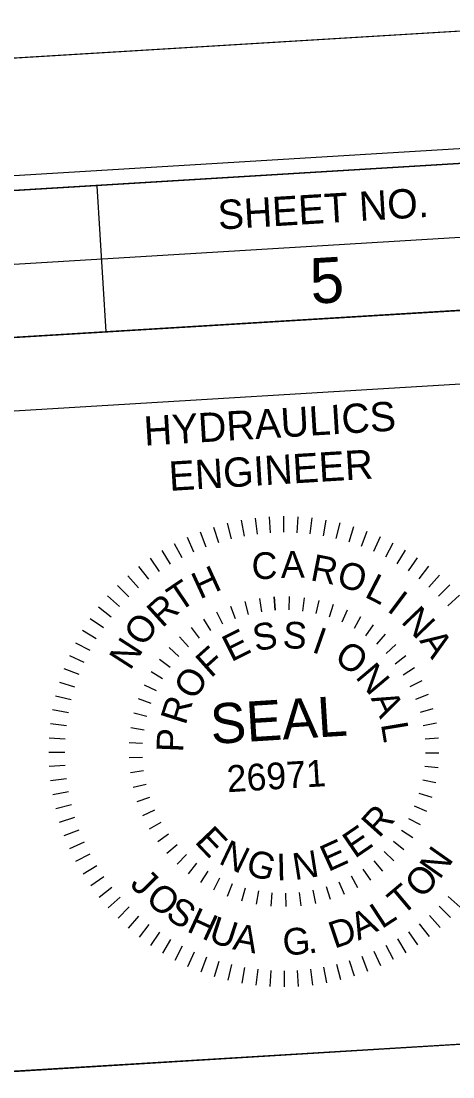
# Model space of a CAD drawing. Extents: x 2111349 to 2114115, y 669753 to 671326.
# Drawn here: x 2113745.9 to 2113819.6, y 670767.4 to 670947.5 of the extents above; entities that cross this region are included whole.
import ezdxf

# ---------------------------------------------------------------- set-up
doc = ezdxf.new("R2010")
doc.units = 0
for name, color, linetype in [('Default', 7, 'Continuous'), ('Exist Roads Curbs', 7, 'Continuous'), ('Exist Roads Curbs Text', 7, 'Continuous'), ('Exist Roads EOP Other Text', 7, 'Continuous'), ('Exist Utilities Power Transformer Cogo Comment', 7, 'Continuous'), ('Exist Utilities Telephone Test Hole SUE LOS A Text', 7, 'Continuous'), ('Exist Utilities Water Test Hole SUE LOS A Text', 7, 'Continuous')]:
    doc.layers.add(name, color=color, linetype=linetype)

msp = doc.modelspace()

# ---------------------------------------------------------------- linework, layer by layer
at = {"layer": 'Default'}
for p, q in [((2113781.1, 670861.87), (2113781.76, 670859.21)), ((2113783.47, 670862.38), (2113783.96, 670859.69)), ((2113785.86, 670862.75), (2113786.2, 670860.03)), ((2113788.28, 670862.97), (2113788.45, 670860.24)), ((2113790.7, 670863.05), (2113790.71, 670860.32)), ((2113793.13, 670862.98), (2113792.97, 670860.25)), ((2113795.54, 670862.77), (2113795.22, 670860.06)), ((2113797.94, 670862.41), (2113797.45, 670859.72)), ((2113800.31, 670861.91), (2113799.66, 670859.25)), ((2113776.47, 670860.42), (2113777.44, 670857.86)), ((2113778.76, 670861.21), (2113779.58, 670858.6)), ((2113802.65, 670861.26), (2113801.84, 670858.64)), ((2113804.94, 670860.47), (2113803.98, 670857.91)), ((2113772.06, 670858.41), (2113773.33, 670856)), ((2113774.23, 670859.49), (2113775.36, 670856.99)), ((2113807.19, 670859.55), (2113806.07, 670857.05)), ((2113809.37, 670858.49), (2113808.1, 670856.07)), ((2113769.94, 670857.22), (2113771.36, 670854.88)), ((2113811.48, 670857.3), (2113810.07, 670854.96)), ((2113767.91, 670855.9), (2113769.47, 670853.65)), ((2113813.52, 670855.99), (2113811.97, 670853.74)), ((2113815.48, 670854.56), (2113813.8, 670852.4)), ((2113764.1, 670852.9), (2113765.92, 670850.86)), ((2113765.96, 670854.46), (2113767.65, 670852.31)), ((2113817.34, 670853.01), (2113815.53, 670850.96)), ((2113762.34, 670851.24), (2113764.28, 670849.31)), ((2113819.11, 670851.35), (2113817.18, 670849.41)), ((2113760.68, 670849.47), (2113762.73, 670847.66)), ((2113789.13, 670849.31), (2113789.27, 670847.04)), ((2113789.27, 670847.04), (2113789.13, 670849.31)), ((2113791.69, 670849.35), (2113791.61, 670847.07)), ((2113794.24, 670849.14), (2113793.94, 670846.88)), ((2113820.78, 670849.59), (2113818.74, 670847.77)), ((2113759.13, 670847.6), (2113761.29, 670845.92)), ((2113781.65, 670847.74), (2113782.44, 670845.6)), ((2113784.09, 670848.51), (2113784.66, 670846.3)), ((2113786.59, 670849.03), (2113786.95, 670846.78)), ((2113796.75, 670848.69), (2113796.24, 670846.46)), ((2113799.21, 670847.99), (2113798.49, 670845.83)), ((2113757.7, 670845.64), (2113759.95, 670844.1)), ((2113779.29, 670846.74), (2113780.28, 670844.69)), ((2113801.59, 670847.06), (2113800.66, 670844.98)), ((2113803.87, 670845.9), (2113802.75, 670843.92)), ((2113774.93, 670844.09), (2113776.29, 670842.26)), ((2113777.05, 670845.52), (2113778.23, 670843.57)), ((2113806.03, 670844.53), (2113804.72, 670842.66)), ((2113756.38, 670843.61), (2113758.73, 670842.2)), ((2113772.96, 670842.46), (2113774.5, 670840.77)), ((2113808.05, 670842.96), (2113806.56, 670841.23)), ((2113755.2, 670841.49), (2113757.62, 670840.22)), ((2113771.16, 670840.65), (2113772.85, 670839.12)), ((2113809.9, 670841.2), (2113808.26, 670839.62)), ((2113754.14, 670839.31), (2113756.64, 670838.19)), ((2113769.53, 670838.67), (2113771.36, 670837.32)), ((2113811.58, 670839.27), (2113809.79, 670837.85)), ((2113753.22, 670837.07), (2113755.78, 670836.1)), ((2113768.11, 670836.55), (2113770.06, 670835.37)), ((2113813.06, 670837.19), (2113811.14, 670835.95)), ((2113752.43, 670834.77), (2113755.04, 670833.96)), ((2113814.34, 670834.97), (2113812.3, 670833.93)), ((2113766.9, 670834.3), (2113768.96, 670833.31)), ((2113751.78, 670832.44), (2113754.44, 670831.79)), ((2113765.91, 670831.94), (2113768.06, 670831.16)), ((2113815.39, 670832.64), (2113813.26, 670831.8)), ((2113751.28, 670830.06), (2113753.97, 670829.58)), ((2113765.16, 670829.5), (2113767.37, 670828.93)), ((2113816.21, 670830.22), (2113814.02, 670829.59)), ((2113750.92, 670827.67), (2113753.63, 670827.34)), ((2113816.8, 670827.73), (2113814.56, 670827.32)), ((2113764.64, 670826.99), (2113766.89, 670826.64)), ((2113750.71, 670825.25), (2113753.43, 670825.09)), ((2113764.37, 670824.45), (2113766.64, 670824.32)), ((2113817.14, 670825.19), (2113814.87, 670825)), ((2113750.64, 670822.83), (2113753.37, 670822.83)), ((2113817.24, 670822.64), (2113814.96, 670822.66)), ((2113750.71, 670820.4), (2113753.45, 670820.57)), ((2113764.34, 670821.89), (2113766.62, 670821.98)), ((2113814.83, 670820.41), (2113817.1, 670820.17)), ((2113764.56, 670819.35), (2113766.82, 670819.65)), ((2113750.94, 670817.99), (2113753.65, 670818.32)), ((2113765.03, 670816.83), (2113767.25, 670817.36)), ((2113816.7, 670817.56), (2113814.47, 670818.02)), ((2113751.31, 670815.59), (2113754, 670816.09)), ((2113765.73, 670814.37), (2113767.89, 670815.11)), ((2113816.06, 670815.08), (2113813.88, 670815.76)), ((2113751.82, 670813.22), (2113754.48, 670813.88)), ((2113815.18, 670812.68), (2113813.08, 670813.57)), ((2113752.48, 670810.89), (2113755.09, 670811.7)), ((2113766.68, 670812), (2113768.75, 670812.94)), ((2113814.09, 670810.38), (2113812.08, 670811.45)), ((2113753.27, 670808.59), (2113755.83, 670809.57)), ((2113767.84, 670809.72), (2113769.82, 670810.86)), ((2113769.22, 670807.57), (2113771.08, 670808.89)), ((2113812.77, 670808.18), (2113810.87, 670809.45)), ((2113754.2, 670806.36), (2113756.7, 670807.49)), ((2113770.8, 670805.56), (2113772.52, 670807.05)), ((2113811.24, 670806.13), (2113809.48, 670807.57)), ((2113755.27, 670804.18), (2113757.69, 670805.45)), ((2113772.57, 670803.71), (2113774.14, 670805.37)), ((2113807.64, 670802.51), (2113806.19, 670804.27)), ((2113809.53, 670804.24), (2113807.91, 670805.84)), ((2113756.47, 670802.07), (2113758.81, 670803.49)), ((2113774.5, 670802.05), (2113775.91, 670803.84)), ((2113776.59, 670800.57), (2113777.82, 670802.5)), ((2113805.59, 670800.98), (2113804.32, 670802.87)), ((2113757.79, 670800.03), (2113760.04, 670801.59)), ((2113778.82, 670799.31), (2113779.85, 670801.34)), ((2113801.1, 670798.54), (2113800.21, 670800.64)), ((2113803.41, 670799.65), (2113802.32, 670801.66)), ((2113759.23, 670798.08), (2113761.38, 670799.77)), ((2113781.15, 670798.26), (2113781.98, 670800.39)), ((2113783.58, 670797.45), (2113784.2, 670799.64)), ((2113786.46, 670799.12), (2113786.05, 670796.87)), ((2113788.6, 670796.54), (2113788.79, 670798.81)), ((2113791.16, 670796.45), (2113791.12, 670798.73)), ((2113793.71, 670796.61), (2113793.46, 670798.87)), ((2113796.23, 670797.01), (2113795.76, 670799.24)), ((2113798.7, 670797.66), (2113798.02, 670799.84)), ((2113760.78, 670796.23), (2113762.83, 670798.04)), ((2113820.88, 670796.35), (2113818.83, 670798.16)), ((2113762.45, 670794.46), (2113764.38, 670796.4)), ((2113819.23, 670794.58), (2113817.29, 670796.51)), ((2113764.22, 670792.8), (2113766.03, 670794.85)), ((2113766.09, 670791.26), (2113767.77, 670793.41)), ((2113815.61, 670791.35), (2113813.91, 670793.5)), ((2113817.46, 670792.91), (2113815.65, 670794.95)), ((2113768.04, 670789.82), (2113769.59, 670792.07)), ((2113813.66, 670789.91), (2113812.09, 670792.16)), ((2113770.08, 670788.51), (2113771.49, 670790.85)), ((2113772.19, 670787.32), (2113773.46, 670789.75)), ((2113809.51, 670787.4), (2113808.24, 670789.82)), ((2113811.62, 670788.59), (2113810.2, 670790.93)), ((2113774.38, 670786.26), (2113775.5, 670788.76)), ((2113776.62, 670785.34), (2113777.59, 670787.9)), ((2113805.1, 670785.39), (2113804.12, 670787.96)), ((2113807.33, 670786.33), (2113806.2, 670788.82)), ((2113778.92, 670784.55), (2113779.73, 670787.17)), ((2113781.25, 670783.9), (2113781.9, 670786.57)), ((2113783.63, 670783.4), (2113784.11, 670786.09)), ((2113798.1, 670783.43), (2113797.6, 670786.12)), ((2113800.47, 670783.94), (2113799.81, 670786.6)), ((2113802.8, 670784.6), (2113801.99, 670787.21)), ((2113786.02, 670783.04), (2113786.35, 670785.76)), ((2113788.44, 670782.83), (2113788.6, 670785.56)), ((2113790.86, 670782.76), (2113790.86, 670785.5)), ((2113793.29, 670782.84), (2113793.12, 670785.57)), ((2113795.7, 670783.06), (2113795.37, 670785.78))]:
    msp.add_line(p, q, dxfattribs=at)
at = {"layer": 'Exist Roads Curbs'}
msp.add_line((2113849.32, 670947.55), (2112168.9, 670845.7), dxfattribs=at)
at = {"layer": 'Exist Roads Curbs Text'}
for p, q in [((2113758.85, 670919.47), (2113760.36, 670894.52)), ((2113634.78, 670899.43), (2113834.47, 670911.53)), ((2113635.54, 670886.95), (2113835.22, 670899.06))]:
    msp.add_line(p, q, dxfattribs=at)
for points in [[(2113833.71, 670924.06), (2112336.45, 670833.32), (2112399.97, 669785.24), (2113897.23, 669875.98)], [(2113634.02, 670911.96), (2113833.71, 670924.06), (2113835.22, 670899.06), (2113635.54, 670886.95)], [(2113736.16, 670880.53), (2113835.98, 670886.58), (2113842.78, 670774.29), (2113742.97, 670768.24)]]:
    msp.add_lwpolyline(points, close=True, dxfattribs=at)
at = {"layer": 'Exist Roads EOP Other Text'}
msp.add_lwpolyline([(2112246.91, 669773.46), (2113909.86, 669874.24), (2113846.03, 670927.31), (2112183.08, 670826.53)], close=True, dxfattribs=at)
at = {"layer": 'Exist Utilities Power Transformer Cogo Comment'}
msp.add_line((2113643.1, 670762.18), (2113842.77, 670774.29), dxfattribs=at)
at = {"layer": 'Exist Utilities Water Test Hole SUE LOS A Text'}
msp.add_lwpolyline([(2112235.14, 669752.71), (2113915.56, 669854.55), (2113849.32, 670947.55), (2112168.9, 670845.7)], close=True, dxfattribs=at)

# ---------------------------------------------------------------- texts
at = {"layer": 'Default'}
for s, height, rotation, p in [('C', 4.56, 0.9334, (2113785.29, 670852.32)), ('A', 4.56, 0.9334, (2113790.27, 670852.54)), ('R', 4.56, 348.9241, (2113795.13, 670852.17)), ('H', 4.56, 24.6441, (2113776.42, 670848.83)), ('O', 4.56, 345.8673, (2113799.62, 670851.14)), ('L', 4.56, 332.731, (2113804.37, 670849.4)), ('T', 4.56, 34.0761, (2113772.88, 670846.62)), ('R', 4.56, 42.237, (2113769.98, 670843.89)), ('I', 4.56, 323.1556, (2113808.2, 670846.99)), ('N', 4.56, 313.8611, (2113810.62, 670844.99)), ('O', 4.56, 55.2938, (2113766.88, 670840.62)), ('E', 4.56, 26.5208, (2113781.78, 670838.14)), ('S', 4.56, 11.2246, (2113785.95, 670839.97)), ('S', 4.56, 355.9283, (2113790.47, 670840.63)), ('I', 4.56, 340.6321, (2113795.36, 670839.95)), ('N', 4.56, 57.2532, (2113764.51, 670836.61)), ('A', 4.56, 304.0936, (2113813.83, 670841.82)), ('F', 4.56, 41.8171, (2113778.3, 670835.34)), ('O', 4.56, 325.3358, (2113799.14, 670838.41)), ('O', 4.56, 57.1133, (2113775.5, 670831.48)), ('N', 4.56, 310.0396, (2113802.84, 670835.58)), ('R', 4.56, 72.4096, (2113773.96, 670827.28)), ('SEAL', 6.841, 3.5765, (2113778.42, 670824.19)), ('A', 4.56, 294.7434, (2113805.56, 670832.01)), ('L', 4.56, 279.4471, (2113807.32, 670827.6)), ('P', 4.56, 87.7058, (2113773.55, 670822.73)), ('26971', 4.557, 3.5765, (2113781.15, 670815.96)), ('R', 4.56, 48.1414, (2113807.01, 670808.01)), ('E', 4.56, 313.6466, (2113775.38, 670807.44)), ('E', 4.56, 34.3703, (2113802.87, 670804.57)), ('N', 4.56, 334.5016, (2113779.44, 670803.89)), ('E', 4.56, 24.3844, (2113798.33, 670802.33)), ('G', 4.56, 343.2679, (2113784.03, 670802.04)), ('N', 4.56, 8.9923, (2113792.63, 670800.96)), ('N', 4.56, 54.8741, (2113817.36, 670800.93)), ('I', 4.56, 1.3627, (2113789.53, 670800.92)), ('J', 4.56, 314.4356, (2113764.33, 670800.12)), ('O', 4.56, 47.4695, (2113814.34, 670797.65)), ('T', 4.56, 40.065, (2113810.93, 670794.78)), ('O', 4.56, 320.6458, (2113766.92, 670797.42)), ('S', 4.56, 328.0503, (2113770.36, 670794.59)), ('L', 4.56, 33.2577, (2113807.48, 670792.56)), ('H', 4.56, 335.216, (2113774.01, 670792.3)), ('A', 4.56, 25.8532, (2113803.47, 670790.62)), ('U', 4.56, 342.0233, (2113777.72, 670790.55)), ('A', 4.56, 349.3084, (2113781.88, 670789.19)), ('D', 4.56, 18.6875, (2113799.38, 670789.25)), ('G', 4.56, 4.1174, (2113790.71, 670788.1)), ('.', 4.56, 11.283, (2113795.01, 670788.39))]:
    msp.add_text(s, height=height, rotation=rotation, dxfattribs=at).set_placement(p)
at = {"layer": 'Exist Roads Curbs Text'}
for s, p in [('SHEET NO.', (2113779.64, 670911.97)), ('HYDRAULICS', (2113767, 670875.09)), ('ENGINEER', (2113771.27, 670867.38))]:
    msp.add_text(s, height=5, rotation=3.4682, dxfattribs=at).set_placement(p)
at = {"layer": 'Exist Utilities Telephone Test Hole SUE LOS A Text'}
msp.add_text('5', height=7.75, rotation=3.4682, dxfattribs=at).set_placement((2113795.47, 670899.3))

doc.saveas('drawing.dxf')
